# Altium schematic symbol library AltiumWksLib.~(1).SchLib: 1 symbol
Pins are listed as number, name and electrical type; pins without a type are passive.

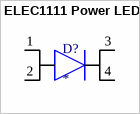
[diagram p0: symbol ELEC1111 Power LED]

## ELEC1111 Power LED
designator D?
An LED used in ELEC1111
pins: 1, 2, 3, 4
